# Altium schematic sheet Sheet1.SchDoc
size A; SheetNumber: 1; SheetTotal: 1
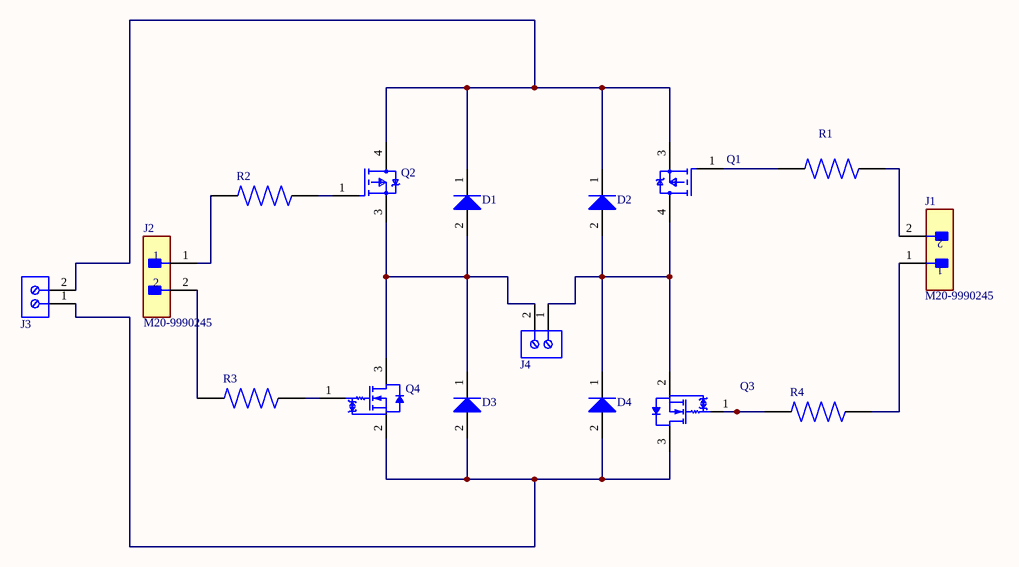
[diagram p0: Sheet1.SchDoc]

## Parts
D1  BAT54HT1G  [ONSC-SOD-323-2-477-02_V]  (value not drawn)
D2  BAT54HT1G  [ONSC-SOD-323-2-477-02_V]  (value not drawn)
D3  BAT54HT1G  [ONSC-SOD-323-2-477-02_V]  (value not drawn)
D4  BAT54HT1G  [ONSC-SOD-323-2-477-02_V]  (value not drawn)
J1  M20-9990245  [FP-M20-9990245-MFG]
J2  M20-9990245  [FP-M20-9990245-MFG]
J3  691214110002  [691214110002]  (value not drawn)
J4  691214110002  [691214110002]  (value not drawn)
Q1  NTB25P06T4G  [FP-418B-04-MFG]  (value not drawn)
Q2  NTB25P06T4G  [FP-418B-04-MFG]  (value not drawn)
Q3  2N7002WT1G  [ONSC-SC-70-3-419-04_V]  (value not drawn)
Q4  2N7002WT1G  [ONSC-SC-70-3-419-04_V]  (value not drawn)
R1  RNC55H3300BSRE6  [RESAD1081W64L635D269]  (value not drawn)
R2  RNC55H3300BSRE6  [RESAD1081W64L635D269]  (value not drawn)
R3  RNC55H3300BSRE6  [RESAD1081W64L635D269]  (value not drawn)
R4  RNC55H3300BSRE6  [RESAD1081W64L635D269]  (value not drawn)

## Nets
NetD1_1: D1.1(K) D2.1(K) J3.2 Q1.3(S) Q2.4(D)
NetD1_2: D1.2(A) D3.1(K) J4.2 Q2.3(S) Q4.3(D)
NetD2_2: D2.2(A) D4.1(K) J4.1 Q1.4(D) Q3.2(S)
NetD3_2: D3.2(A) D4.2(A) J3.1 Q3.3(D) Q4.2(S)
NetJ1_1: J1.1 R4.2
NetJ1_2: J1.2 R1.2
NetJ2_1: J2.1 R2.1
NetJ2_2: J2.2 R3.1
NetQ1_1: Q1.1(G) R1.1
NetQ2_1: Q2.1(G) R2.2
NetQ3_1: Q3.1(G) R4.1
NetQ4_1: Q4.1(G) R3.2

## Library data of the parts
D1-D4 = CMP-1055-00462-1: Schottky Barrier Diode, 2-Pin SOD-323, Pb-Free, Tape and Reel; Manufacturer: On Semiconductor; Configuration: Single; trr Max (ns): 5; IFSM Max (A): 0.6
J1 J2 = CMP-15831-000105-1: CONN HEADER VERT 2POS 2.54MM; Working Voltage: 750V; Gender: Male; Number of Poles: 2; Current Rating: 3A; Mated Stacking Heights: 16.54mm; Contact Resistance: 25mR; Connector Type: Male Pin; Insulation Resistance: 10GR; Mating Cycles: 300; Voltage: 50V
J3 J4 = CMP-1502-02464-2: NexarPartId: 18818288; Plating: Brass, Steel; Current: 10A; Pitch: 3.5052mm; Number of Levels: 1; Number of Contacts: 2; Wire Gauge (Min): 16AWG; Voltage: 300V; Wire Gauge (Max): 24AWG; Stripping Length: -6mm
Q1 Q2 = CMP-1058-00100-2: Manufacturer Lifecycle Status: ACTIVE; NexarPartId: 341266; Turn-On Delay Time: 14ns; Number of Elements: 1; Max Junction Temperature (Tj): 175°C; Power Dissipation: 120W; Voltage Rating (DC): -60V; Gate to Source Voltage (Vgs): 15V; Drain to Source Resistance: 65mΩ; Current Rating: -25A; Turn-Off Delay Time: 43ns; Continuous Drain Current (ID): 27.5A; Rds On Max: 82mΩ; Rise Time: 72ns; Fall Time: 190ns; Input Capacitance: 1.68nF; Element Configuration: Single
Q3 Q4 = CMP-1058-00618-1: Small Signal MOSFET, 60 V, 340 mA, Single, N-Channel, 3-Pin SC70, Pb-Free, Tape and Reel; Manufacturer: On Semiconductor; Crss Typ (pF): 2.2; Coss Typ (pF): 4.2; VGS(th) Max (V): 2.5; Channel Polarity: N Channel; ID Max (A): 0.34; VGS Max (V): 20; V(BR)DSS Min (V): 60; Ciss Typ (pF): 24.5
R1-R4 = RNC55H3300BSRE6: 330 Ohms Â±0.1% 0.125W, 1/8W Through Hole Resistor Axial Military, Moisture Resistant, Weldable Metal Film; MF: Vishay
